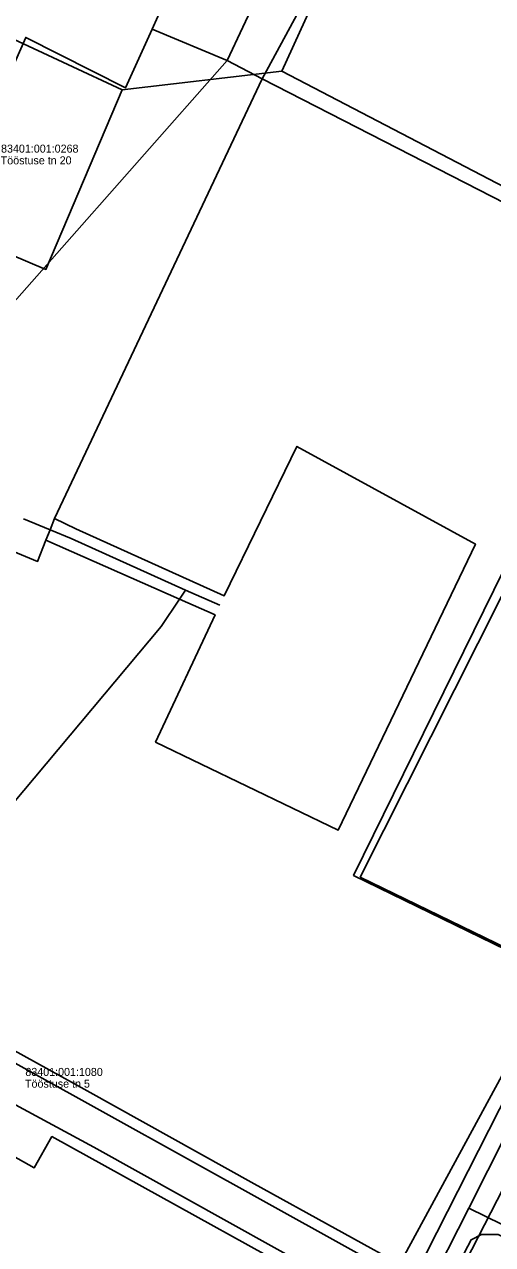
# Model space of a CAD drawing. Extents: x 580119 to 583377, y 6518915 to 6520820.
# Drawn here: x 581401 to 581488.7, y 6520226.6 to 6520455.4 of the extents above; entities that cross this region are included whole.
import ezdxf

# ---------------------------------------------------------------- set-up
doc = ezdxf.new("R2010")
doc.units = 0
for name, color, linetype in [('L_AADRESS', 7, 'Continuous'), ('MPOHULIIN', 7, 'Continuous'), ('PIIR', 7, 'Continuous'), ('Tee Liiklusala', 7, 'Continuous'), ('Tee Rada Püsikate', 7, 'Continuous'), ('Tee Sport', 7, 'Continuous'), ('Tee Tänav Kruuskate', 7, 'Continuous'), ('Tee Tänav Püsikate', 7, 'Continuous'), ('TUNNUS', 7, 'Continuous')]:
    doc.layers.add(name, color=color, linetype=linetype)

msp = doc.modelspace()

# ---------------------------------------------------------------- linework, layer by layer
at = {"layer": 'MPOHULIIN'}
msp.add_lwpolyline([(581573.43, 6520394.97), (581563.99, 6520380.62), (581550.36, 6520353.89), (581536.13, 6520325.71), (581518.2, 6520290.77), (581498.96, 6520253.33), (581478.9, 6520214.22), (581458.59, 6520174.68)], dxfattribs=at)
at = {"layer": 'PIIR'}
for points in [[(581449.24, 6520446.57), (581543.55, 6520653.33), (581657.24, 6520583.27), (581558.12, 6520389.79)], [(581405.05, 6520409.44), (581384.33, 6520418.25), (581399, 6520452.6), (581419.35, 6520443.1)], [(581500.71, 6520277.24), (581462.65, 6520295.82), (581494.52, 6520360.71), (581533.26, 6520341.75)]]:
    msp.add_lwpolyline(points, close=True, dxfattribs=at)
for points in [[(581400.45, 6520092.33), (581500.71, 6520277.24), (581533.26, 6520341.75), (581558.12, 6520389.79), (581657.24, 6520583.27)], [(581384.33, 6520418.25), (581405.05, 6520409.44), (581419.35, 6520443.1), (581449.24, 6520446.57), (581558.12, 6520389.79), (581533.26, 6520341.75), (581494.52, 6520360.71), (581462.65, 6520295.82), (581500.71, 6520277.24), (581400.45, 6520092.33)]]:
    msp.add_lwpolyline(points, dxfattribs=at)
at = {"layer": 'Tee Liiklusala'}
for points in [[(581372.37, 6520277.77), (581412.75, 6520255.44), (581444.02, 6520238.01), (581474.39, 6520221.23), (581513.33, 6520297.97), (581534.24, 6520338.35), (581559.43, 6520386.73), (581591.38, 6520450.18), (581592.88, 6520453.16), (581609.8, 6520486.3), (581623.7, 6520512.67), (581636.83, 6520537.65), (581653.69, 6520569.75), (581656.07, 6520574.59), (581657.42, 6520577.86), (581657.31, 6520580.54), (581656.47, 6520584.5), (581655.72, 6520587.99), (581655.58, 6520589.38), (581654.54, 6520590.67), (581652.74, 6520592.05), (581631.26, 6520605.03)], [(581385.7, 6520417.64), (581401.28, 6520452.92), (581419.94, 6520443.5), (581424.92, 6520454.45), (581427.08, 6520459.21), (581434.62, 6520475.73), (581441.54, 6520491), (581445.31, 6520489.53), (581448.18, 6520489.07), (581449.78, 6520489.48), (581452.24, 6520491.26), (581455.63, 6520496.18), (581463.49, 6520510.61), (581473.25, 6520530.95), (581491.6, 6520571.38), (581506.42, 6520605.03)], [(581519.35, 6520605.03), (581466.9, 6520491.98), (581466.71, 6520489.83), (581466.93, 6520487.11), (581468.42, 6520484.34), (581462.17, 6520475.88), (581445.53, 6520445.19), (581406.67, 6520362.76), (581405.81, 6520360.63), (581405.04, 6520358.69), (581403.47, 6520354.7), (581398.2, 6520356.89)], [(581398.16, 6520073.66), (581402.55, 6520082.81), (581422.36, 6520120.09), (581439.19, 6520152.49), (581449.34, 6520172.35), (581469.76, 6520211.65), (581406.17, 6520246.86), (581402.87, 6520241), (581366.58, 6520261.36)], [(581520.48, 6520213.45), (581489.72, 6520228.51), (581486.61, 6520228.5), (581484.66, 6520227.52), (581458.05, 6520176.72)]]:
    msp.add_lwpolyline(points, dxfattribs=at)
at = {"layer": 'Tee Rada Püsikate'}
for points in [[(581561.96, 6520385.36), (581559.43, 6520386.73), (581445.53, 6520445.19), (581438.96, 6520448.57)], [(581374.05, 6520280.84), (581385.74, 6520293.71), (581426.65, 6520342.47), (581430.06, 6520347.6), (581431.18, 6520349.28)]]:
    msp.add_lwpolyline(points, dxfattribs=at)
at = {"layer": 'Tee Sport'}
for points in [[(581405.04, 6520358.69), (581405.81, 6520360.63), (581406.67, 6520362.76), (581410.66, 6520360.81), (581438.44, 6520348.24), (581452.03, 6520376.24), (581485.46, 6520357.93), (581459.75, 6520304.29), (581425.59, 6520320.81), (581436.73, 6520344.65), (581430.06, 6520347.6)], [(581524.36, 6520332.21), (581497.73, 6520279.03), (581463.9, 6520295.5), (581490.35, 6520348.1)]]:
    msp.add_lwpolyline(points, close=True, dxfattribs=at)
at = {"layer": 'Tee Tänav Kruuskate'}
msp.add_lwpolyline([(581484.21, 6520233.43), (581521.2, 6520215.32), (581523.09, 6520214.77), (581527.75, 6520213.4)], dxfattribs=at)
at = {"layer": 'Tee Tänav Püsikate'}
for points in [[(581438.96, 6520448.57), (581453.64, 6520479.9), (581468.07, 6520509.17), (581483.86, 6520543.58), (581510.84, 6520605.03)], [(581438.96, 6520448.57), (581424.92, 6520454.45)], [(581373.27, 6520374.09), (581438.96, 6520448.57)], [(581431.18, 6520349.28), (581409.77, 6520358.99), (581405.81, 6520360.63), (581400.87, 6520362.67)], [(581437.6, 6520346.5), (581431.18, 6520349.28)], [(581516.22, 6520296.85), (581484.21, 6520233.43)], [(581476.32, 6520217.81), (581371.43, 6520276.06)], [(581367.54, 6520270.01), (581414.01, 6520244.9), (581473.27, 6520211.86)], [(581484.21, 6520233.43), (581476.32, 6520217.81)]]:
    msp.add_lwpolyline(points, dxfattribs=at)

# ---------------------------------------------------------------- texts
at = {"layer": 'L_AADRESS'}
for s, p in [('Tööstuse tn 20', (581396.58, 6520429.13)), ('Tööstuse tn 5', (581401.13, 6520256.03))]:
    msp.add_text(s, height=1.5, dxfattribs=at).set_placement(p)
at = {"layer": 'TUNNUS'}
for s, p in [('83401:001:0268', (581396.64, 6520431.33)), ('83401:001:1080', (581401.19, 6520258.23))]:
    msp.add_text(s, height=1.5, dxfattribs=at).set_placement(p)

doc.saveas('drawing.dxf')
